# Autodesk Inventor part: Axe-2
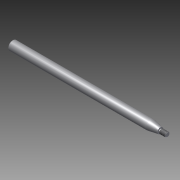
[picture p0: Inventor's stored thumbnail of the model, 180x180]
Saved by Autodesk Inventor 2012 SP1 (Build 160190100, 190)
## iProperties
Created: 2012-06
Part Number: Axe-2
Material: Default
Document SubType Name: Modeling
Designer: Bruno
Density: 1 g/cm^3
Author: Bruno
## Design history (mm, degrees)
sketch "Esquisse1"
  geometry: L1 (60.184, 4.5)-(80.033, 1); L2 (81.033, 0.5)-(81.033, -0.038); L3 (80.033, -0.038)-(81.033, -0.038); L4 (-48.474, -3.5)-(91.078, -3.5); L5 (-48.474, 3.5)-(-47.474, 4.5); L6 (-48.474, -3.5)-(-48.474, 3.5); L7 (-47.474, 4.5)-(60.184, 4.5); L8 (80.033, 1)-(80.033, -0.038); L9 (81.033, 0.5)-(90.578, 0.5); L10 (91.078, 0)-(91.078, -3.5); L11 (91.078, 0)-(90.578, 0.5); 1 further point
  constraints: 22 end point, 6 perpendicular, 2 point on line
  dimensions: "d31" = 0.5 distance of L10.start point (91.078, 0.5); "d32" = 0.5 distance of L9.end point (91.078, 0.5) (= d31); "d40" = 8 distance between parallel lines of L7 L4; "d43" = 4 distance between parallel lines of L4 L9; "d46" = 1 horizontal distance of L5.end L5.start; "d47" = 1 horizontal distance of L5.end L5.start
revolve "Révolution1" sketch "Esquisse1" stored, may be unused: angle "d7" = 90 deg
sketch "Esquisse3"
  geometry: C1 r 7 at (0, 0) reference; 1 further point
  constraints: 1 coincident
hole "Perçage2" sketch "Esquisse3" at (0, 0) diameter "d33" = 4.917; stored, may be unused: countersink angle "d37" = 90 deg, drill point angle "d39" = 118 deg; dims "d34" = 10, "d35" = 4, "d36" = 2, "d38" = 15
feature "Filetage3" dims "d44" = 10, "d45" = 0
node "Solide1"
